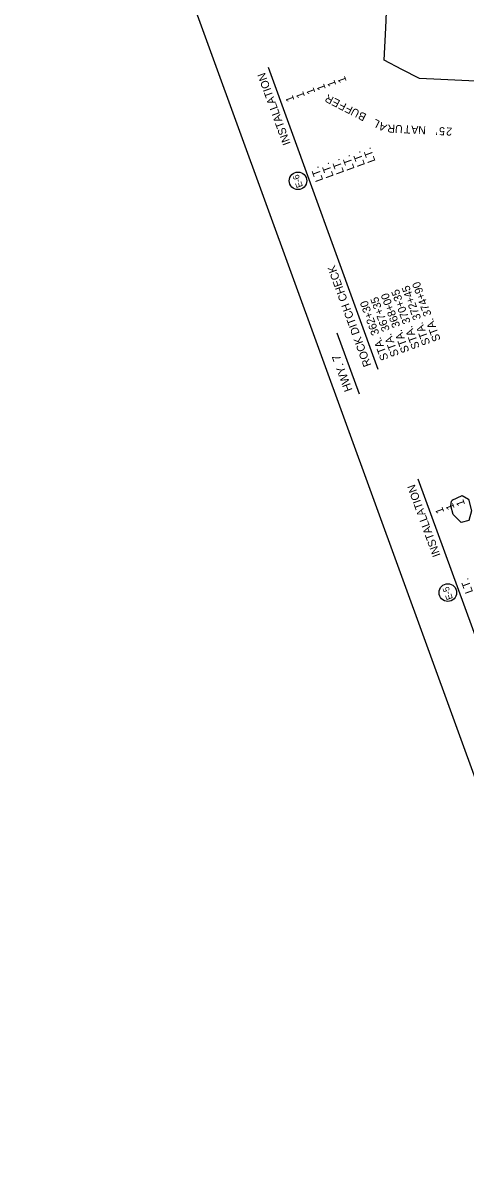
# Model space of a CAD drawing. Extents: x 960650 to 962115, y 1906452 to 1908757.
# Drawn here: x 960650 to 960982, y 1907002 to 1907870 of the extents above; entities that cross this region are included whole.
import ezdxf

# ---------------------------------------------------------------- set-up
doc = ezdxf.new("R2010")
doc.units = 0
for name, color, linetype in [('1', 7, 'Continuous'), ('44', 7, 'Continuous'), ('NO PLOT', 7, 'Continuous'), ('R_Draft', 7, 'Continuous'), ('S_STREAM', 7, 'Continuous'), ('S_TREE', 7, 'Continuous')]:
    doc.layers.add(name, color=color, linetype=linetype)

msp = doc.modelspace()

# ---------------------------------------------------------------- linework, layer by layer
at = {"layer": '1'}
for centre in [(960855.76, 1907751.44), (960968.15, 1907442.66)]:
    msp.add_circle(centre, 6.61, dxfattribs=at)
at = {"layer": '44'}
for p, q in [((960915.99, 1907610.01), (960833.56, 1907836.49)), ((960901.91, 1907591.39), (960885.21, 1907637.29)), ((961028.38, 1907301.23), (960945.95, 1907527.7))]:
    msp.add_line(p, q, dxfattribs=at)
at = {"layer": 'NO PLOT'}
msp.add_lwpolyline([(961135.09, 1906901.21), (960730.12, 1908013.86), (960776.54, 1908030.76), (960709.57, 1908214.75), (960723.29, 1908219.74), (960649.59, 1908422.25), (961079.18, 1908578.6), (961182.12, 1908295.76), (961109.77, 1908269.43), (961255.13, 1907870.06), (961327.48, 1907896.39), (961425.36, 1907627.47), (961369.64, 1907607.19), (961486.84, 1907285.2), (961542.56, 1907305.48), (961624.82, 1907079.46)], close=True, dxfattribs=at)
msp.add_lwpolyline([(961135.09, 1906901.21), (960730.12, 1908013.86), (960776.54, 1908030.76), (960709.57, 1908214.75), (960723.29, 1908219.74), (960649.59, 1908422.25), (961079.18, 1908578.6), (961182.12, 1908295.76), (961109.77, 1908269.43), (961255.13, 1907870.06), (961327.48, 1907896.39), (961425.36, 1907627.47), (961369.64, 1907607.19), (961486.84, 1907285.2), (961542.56, 1907305.48), (961624.82, 1907079.46)], close=True, dxfattribs=at)
msp.add_lwpolyline([(961135.09, 1906901.21), (960730.12, 1908013.86), (960776.54, 1908030.76), (960709.57, 1908214.75), (960723.29, 1908219.74), (960649.59, 1908422.25), (961079.18, 1908578.6), (961182.12, 1908295.76), (961109.77, 1908269.43), (961255.13, 1907870.06), (961327.48, 1907896.39), (961425.36, 1907627.47), (961369.64, 1907607.19), (961486.84, 1907285.2), (961542.56, 1907305.48), (961624.82, 1907079.46)], close=True, dxfattribs=at)
msp.add_lwpolyline([(961135.09, 1906901.21), (960730.12, 1908013.86), (960776.54, 1908030.76), (960709.57, 1908214.75), (960723.29, 1908219.74), (960649.59, 1908422.25), (961079.18, 1908578.6), (961182.12, 1908295.76), (961109.77, 1908269.43), (961255.13, 1907870.06), (961327.48, 1907896.39), (961425.36, 1907627.47), (961369.64, 1907607.19), (961486.84, 1907285.2), (961542.56, 1907305.48), (961624.82, 1907079.46)], close=True, dxfattribs=at)
msp.add_lwpolyline([(961135.09, 1906901.21), (960730.12, 1908013.86), (960776.54, 1908030.76), (960709.57, 1908214.75), (960723.29, 1908219.74), (960649.59, 1908422.25), (961079.18, 1908578.6), (961182.12, 1908295.76), (961109.77, 1908269.43), (961255.13, 1907870.06), (961327.48, 1907896.39), (961425.36, 1907627.47), (961369.64, 1907607.19), (961486.84, 1907285.2), (961542.56, 1907305.48), (961624.82, 1907079.46)], close=True, dxfattribs=at)
at = {"layer": 'S_STREAM'}
msp.add_lwpolyline([(961059, 1907787.27), (961049.99, 1907786.16), (961032.27, 1907793.42), (961021.24, 1907809.22), (961010.21, 1907825.01), (960994.4, 1907825.81), (960978.59, 1907826.61), (960962.78, 1907827.4), (960946.97, 1907828.2), (960933.72, 1907835.05), (960920.48, 1907841.89), (960921.55, 1907866.06), (960922.63, 1907890.23), (960900.34, 1907892.36), (960878.06, 1907894.49), (960855.77, 1907896.62), (960833.49, 1907898.75)], dxfattribs=at)
at = {"layer": 'S_TREE'}
msp.add_lwpolyline([(960971.41, 1907512.07), (960978.89, 1907515.56), (960983.71, 1907512.82), (960985.86, 1907503.99), (960983.93, 1907496.61), (960978.23, 1907495.34), (960972.15, 1907501.22), (960970.29, 1907507.67), (960970.9, 1907511.32), (960972.09, 1907512.54)], dxfattribs=at)

# ---------------------------------------------------------------- texts
at = {"layer": '1'}
for s, p in [('E-6 ', (960859.49, 1907747.27)), ('E-5 ', (960971.99, 1907438.2))]:
    msp.add_text(s, height=4.8, rotation=110, dxfattribs=at).set_placement(p)
at = {"layer": '44'}
for s, height, p in [('INSTALLATION', 6, (960850.33, 1907779.42)), ('1', 6, (960884.48, 1907823.3)), ('1', 6, (960892.31, 1907826.15)), ('1', 6, (960860.99, 1907814.75)), ('1', 6, (960868.82, 1907817.6)), ('1', 6, (960876.65, 1907820.45)), ('1', 6, (960853.16, 1907811.9)), ('LT.', 6, (960906.11, 1907763.39)), ('LT.', 6, (960913.94, 1907766.24)), ('LT.', 6, (960882.62, 1907754.84)), ('LT.', 6, (960890.45, 1907757.69)), ('LT.', 6, (960898.28, 1907760.54)), ('LT.', 6, (960874.79, 1907751.99)), ('ROCK DITCH CHECK', 6, (960910.82, 1907613.23)), ('STA. 370+35', 6, (960947.23, 1907626.49)), ('STA. 372+45', 6, (960955.06, 1907629.34)), ('STA. 374+90', 6, (960962.89, 1907632.19)), ('STA. 362+30', 6, (960923.74, 1907617.94)), ('STA. 367+35', 6, (960931.57, 1907620.79)), ('STA. 368+00', 6, (960939.4, 1907623.64)), ('HWY. 7', 6.25, (960896.71, 1907594.65)), ('INSTALLATION', 6, (960962.72, 1907470.64)), ('1', 6, (960965.48, 1907503.09)), ('1', 6, (960973.31, 1907505.94)), ('1', 6, (960981.14, 1907508.79)), ('LT.', 6, (960987.11, 1907443.18))]:
    msp.add_text(s, height=height, rotation=110, dxfattribs=at).set_placement(p)
at = {"layer": 'R_Draft'}
for s, rotation, p in [('R', 152.66648, (960883.1, 1907813.89)), ('E', 152.66648, (960887.88, 1907811.42)), ('F', 152.66648, (960892.67, 1907808.94)), ('F', 152.66648, (960897.45, 1907806.47)), ('U', 152.66648, (960902.57, 1907803.82)), ('B', 152.66648, (960907.61, 1907801.22)), ('L', 152.66648, (960917.72, 1907795.99)), ('A', 152.66648, (960922.93, 1907793.3)), ('R', 177.11488, (960928.7, 1907793.42)), ('U', 177.11488, (960934.45, 1907793.13)), ('T', 177.11488, (960940.3, 1907792.84)), ('A', 177.11488, (960946.16, 1907792.54)), ('N', 177.11488, (960951.82, 1907792.26)), ('5', 177.11488, (960966.11, 1907791.54)), ('2', 177.11488, (960971.49, 1907791.27)), ("'", 177.11488, (960960.74, 1907791.81))]:
    msp.add_text(s, height=6, rotation=rotation, dxfattribs=at).set_placement(p)

doc.saveas('drawing.dxf')
